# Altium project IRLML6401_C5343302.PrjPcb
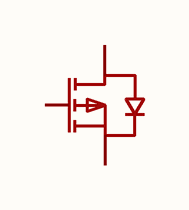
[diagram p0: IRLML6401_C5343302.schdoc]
1 sheet, 1 parts. Net scope: global (net labels, ports and power ports of the same name join across sheets).

## Sheet IRLML6401_C5343302.schdoc
size 127 x 101 mm

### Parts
Q?  irlml6401_c5343302  [SOT-23-3_L2.9-W1.3-P1.90-LS2.4-BR]  (value not drawn)

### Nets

Not connected (* = marked no-connect by the designer): Q? 1(G) 2(S) 3(D)

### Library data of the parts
Q? = irlml6401_c5343302: 数量:1个P沟道;漏源电压(Vdss):12V;连续漏极电流(Id):4.3A;导通电阻(RDS(on)):40mΩ@4.5V;耗散功率(Pd):1.56W;阈值电压(Vgs(th)):600mV;; Manufacturer: MSKSEMI(美森科); AddInBom: yes; ModelId: c62791f0466c4ae2a892c056b845b0ca; ModelName: SOT-23-3P_L2.9-W1.3-H1.0-LS2.4-P0.95; ModelTransform: 98.425,114.173,0,180,0,0,0.0005,-0.0005,0; Number: 1个P沟道; Drain to Source Voltage: 12V; Current - Continuous Drain(Id): 4.3A; Pd - Power Dissipation: 1.56W; Gate Threshold Voltage (Vgs(th)): 600mV; Gate Charge(Qg): 9.6nC@4.5V; Input Capacitance(Ciss): 850pF; Reverse Transfer Capacitance (Crss@Vds): 55pF; Type: P沟道; Output Capacitance(Coss): 70pF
